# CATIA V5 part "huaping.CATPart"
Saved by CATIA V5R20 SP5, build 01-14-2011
Part number: Part1
Material "DS Light Blue": density 7860 kg/m3, Young's modulus 2e+11 Pa, Poisson ratio 0.266
Bounding box of the stored display mesh (mm): x -31.621 to 31.621, y -31.621 to 31.589, z 0 to 100
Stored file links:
  E:\huaping.CATPart
  C:\Program Files\Dassault Systemes\B20\intel_a\startup\materials\Catalog.CATMaterial
  C:\Program Files\Dassault Systemes\B20\intel_a\startup\materials\blue_env_512x512.jpg
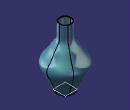
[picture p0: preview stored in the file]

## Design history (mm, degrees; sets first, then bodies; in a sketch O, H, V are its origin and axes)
Body1 (main body), material "DS Light Blue"
  Plane1: type Offset, RefPlane xy-plane, Offset 20
  Plane2: type Offset, RefPlane Plane1, Offset 20
  Plane3: type Offset, RefPlane Plane2, Offset 20
  Plane4: type Offset, RefPlane Plane3, Offset 20
  Plane5: type Offset, RefPlane Plane4, Offset 20
  Sketch1 on xy-plane, origin (0, 0, 0), H (1, 0, 0), V (0, 1, 0)
    circle A1 centre (0, 0) radius 14.1421
    radius A1 = 14.1421
  Sketch2 on Plane1, origin (0, 0, 20), H (1, 0, 0), V (0, 1, 0)
    circle A1 centre (0, 0) radius 22.3607
    radius A1 = 22.3607
  Sketch3 on Plane2, origin (0, 0, 40), H (1, 0, 0), V (0, 1, 0)
    circle A1 centre (0, 0) radius 31.6228
    radius A1 = 31.6228
  Sketch4 on Plane3, origin (0, 0, 60), H (1, 0, 0), V (0, 1, 0)
    circle A1 centre (0, 0) radius 20
    point P1 (20, 0)
    radius A1 = 20
    coincidence: A1 P1, P1 H
  Sketch5 on Plane4, origin (0, 0, 80), H (1, 0, 0), V (0, 1, 0)
    circle A1 centre (0, 0) radius 10
    radius A1 = 10
  Sketch6 on Plane5, origin (0, 0, 100), H (1, 0, 0), V (0, 1, 0)
    circle A1 centre (0, 0) radius 10
    radius A1 = 10
  Loft1: solid, Sections (Sketch1; Sketch2; Sketch3; Sketch4; Sketch5; Sketch6)
  Shell1: ExtOffset 0, Face face of Loft1, IntOffset 1
Body2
